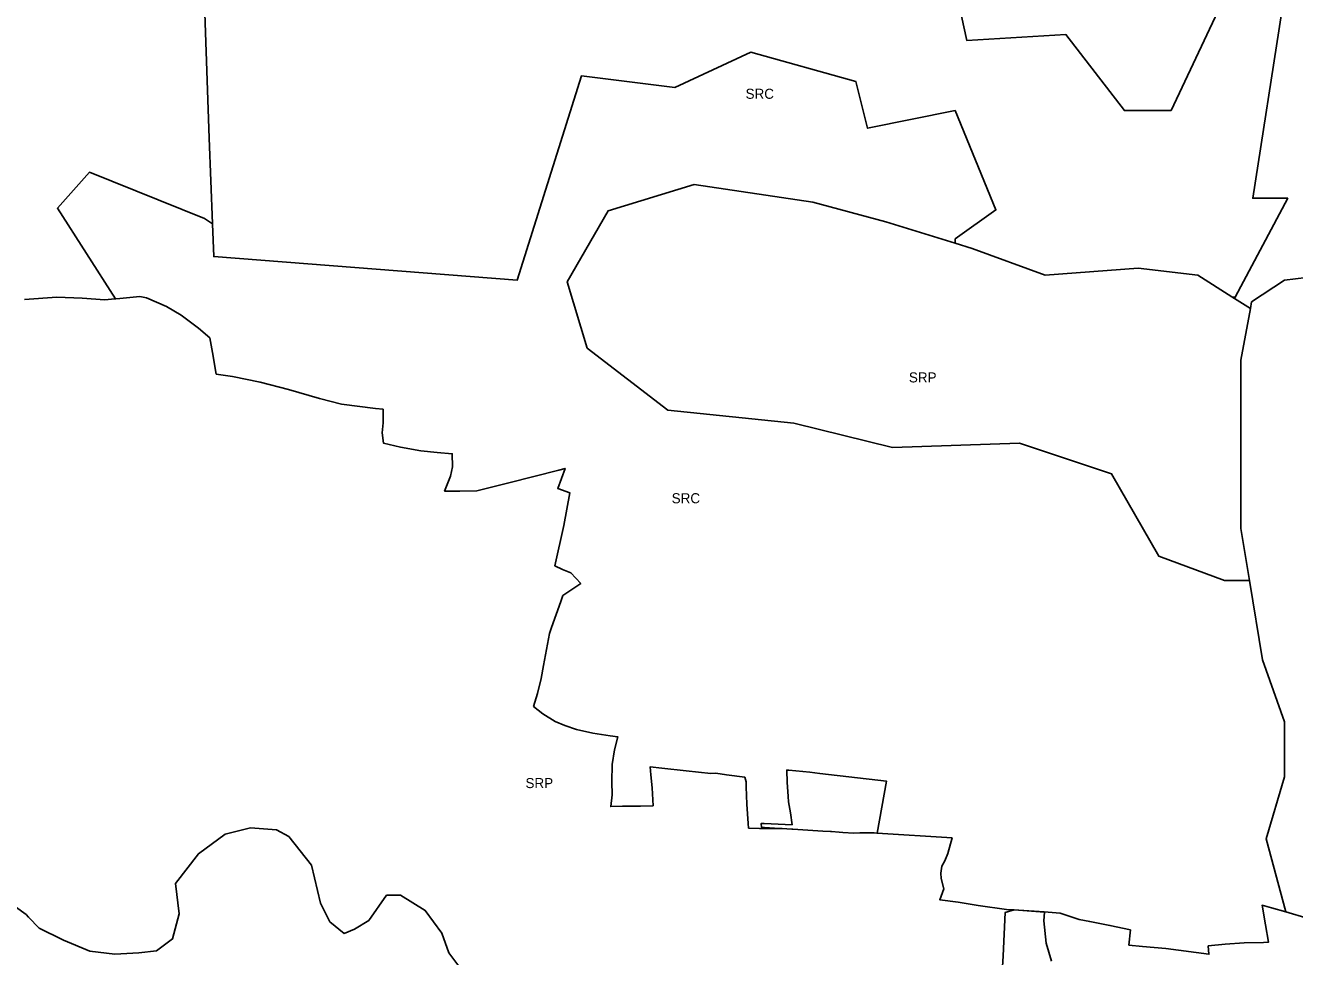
# Model space of a CAD drawing. Extents: x 598968 to 613553, y 4409678 to 4430833.
# Drawn here: x 601335 to 602848, y 4410591 to 4411701 of the extents above; entities that cross this region are included whole.
import ezdxf

# ---------------------------------------------------------------- set-up
doc = ezdxf.new("R2010")
doc.units = 0
for name, color, linetype in [('1', 7, 'Continuous'), ('Sòl Rústic Comú', 7, 'Continuous'), ('Sòl Rústic Protegit', 7, 'Continuous'), ('Sòl Rústic Protegit - Alt Nivell de Protecció', 7, 'Continuous')]:
    doc.layers.add(name, color=color, linetype=linetype)

msp = doc.modelspace()

# ---------------------------------------------------------------- linework, layer by layer
at = {"layer": '1'}
msp.add_lwpolyline([(602346.7629, 4410738.7608), (602350.3001, 4410738.7402), (602361.6351, 4410800.3432), (602282.0101, 4410809.5702), (602270.0801, 4410811.4102), (602244.9901, 4410813.7002), (602242.5701, 4410813.7002), (602243.2701, 4410799.0352), (602243.7841, 4410788.2652), (602244.3001, 4410782.1302), (602244.8161, 4410775.9952), (602247.0051, 4410762.7602), (602248.9791, 4410748.6272), (602215.8541, 4410750.1482), (602212.1451, 4410750.1482), (602212.3801, 4410745.1402), (602216.2601, 4410745.2502), (602228.1091, 4410744.5942), (602237.0101, 4410744.2102), (602248.5381, 4410743.465), (602249.0359, 4410743.4328), (602249.7101, 4410743.3892), (602285.8001, 4410741.0252), (602294.6517, 4410740.4454), (602294.6635, 4410740.4446), (602295.8981, 4410740.3638), (602305.2495, 4410739.7514), (602309.2523, 4410739.4892), (602322.5201, 4410738.6202), (602329.7301, 4410738.8602), (602345.9551, 4410738.7654)], close=True, dxfattribs=at)
at = {"layer": 'Sòl Rústic Comú'}
for points in [[(602422.3725, 4411843.1854), (602457.1223, 4411683.1854), (602575.3735, 4411690.1856), (602644.9363, 4411599.6856), (602700.5619, 4411599.6856), (602756.1879, 4411717.6858)], [(602756.1879, 4411717.6858), (602700.5619, 4411599.6856), (602644.9363, 4411599.6856), (602575.3735, 4411690.1856), (602457.1223, 4411683.1854), (602422.3725, 4411843.1854)], [(601547.3631, 4411773.1842), (601554.2999, 4411566.684), (601558.2995, 4411465.184), (601558.3193, 4411464.6848), (601559.8619, 4411425.684), (601921.5531, 4411397.6844), (601998.0547, 4411641.1848), (602109.3683, 4411627.1848), (602199.7445, 4411669.185), (602324.9957, 4411634.1852), (602338.8705, 4411578.6852), (602443.1843, 4411599.6852), (602491.9343, 4411481.1852), (602443.1837, 4411446.6852), (602443.1837, 4411441.6852), (602463.5589, 4411435.1852), (602550.5597, 4411403.6852), (602661.3109, 4411411.6854), (602732.4991, 4411403.6856), (602772.9369, 4411377.6856), (602777.0619, 4411377.1856), (602839.6879, 4411495.1858), (602797.9375, 4411495.1856), (602832.7513, 4411717.686)], [(602832.7513, 4411717.686), (602797.9375, 4411495.1856), (602839.6879, 4411495.1858), (602777.0619, 4411377.1856), (602772.9369, 4411377.6856), (602795.1245, 4411363.6856), (602796.6245, 4411371.6856), (602835.8125, 4411397.6856), (602875.0005, 4411402.1858)]]:
    msp.add_lwpolyline(points, dxfattribs=at)
msp.add_lwpolyline([(602443.1837, 4411441.6852), (602443.1837, 4411446.6852), (602491.9343, 4411481.1852), (602443.1843, 4411599.6852), (602338.8705, 4411578.6852), (602324.9957, 4411634.1852), (602199.7445, 4411669.185), (602109.3683, 4411627.1848), (601998.0547, 4411641.1848), (601921.5531, 4411397.6844), (601559.8619, 4411425.684), (601558.3193, 4411464.6848), (601548.9245, 4411471.184), (601411.6733, 4411526.1838), (601373.5477, 4411483.1838), (601442.8415, 4411375.2134), (601442.8605, 4411375.1838), (601447.8605, 4411375.6838), (601471.6107, 4411378.1838), (601479.4859, 4411376.6838), (601503.6735, 4411366.1838), (601520.9237, 4411355.6838), (601541.7363, 4411340.1838), (601554.9865, 4411328.6838), (601558.4865, 4411311.1838), (601562.7989, 4411285.6838), (601582.0491, 4411282.6838), (601615.1119, 4411276.1838), (601648.9247, 4411267.1838), (601685.9875, 4411256.684), (601712.1129, 4411249.684), (601752.6757, 4411244.684), (601761.5509, 4411243.684), (601761.8007, 4411227.684), (601760.3631, 4411215.684), (601762.2381, 4411203.184), (601782.3009, 4411198.684), (601806.6135, 4411194.184), (601825.9887, 4411192.184), (601843.9889, 4411190.684), (601844.4889, 4411175.184), (601841.8639, 4411164.184), (601834.8637, 4411146.184), (601852.8639, 4411146.184), (601873.2391, 4411146.684), (601911.3645, 4411156.1842), (601970.9277, 4411171.1842), (601978.4903, 4411173.1842), (601969.6777, 4411149.1842), (601984.0527, 4411144.1842), (601976.9901, 4411105.1842), (601966.1147, 4411057.1842), (601975.2399, 4411052.6842), (601985.3649, 4411048.6842), (601997.1149, 4411036.1842), (601985.3023, 4411028.1842), (601975.7397, 4411021.6842), (601973.5521, 4411014.6842), (601962.3019, 4410983.684), (601959.9893, 4410976.684), (601952.6767, 4410938.184), (601949.8015, 4410922.684), (601945.4265, 4410905.184), (601940.9889, 4410889.684), (601952.1139, 4410880.684), (601966.7391, 4410871.684), (601977.9891, 4410866.684), (601991.9267, 4410862.184), (602011.5519, 4410857.684), (602031.9897, 4410854.684), (602041.3647, 4410853.184), (602037.4271, 4410837.684), (602034.6145, 4410820.184), (602034.1769, 4410799.684), (602034.6769, 4410784.184), (602032.9269, 4410770.184), (602046.9895, 4410770.684), (602068.4273, 4410770.684), (602083.3023, 4410771.184), (602082.1149, 4410792.684), (602080.6775, 4410808.184), (602079.8651, 4410817.684), (602093.8027, 4410816.184), (602122.6155, 4410812.6842), (602152.0533, 4410809.6842), (602158.0533, 4410810.1842), (602170.9285, 4410808.1842), (602192.4911, 4410805.1842), (602194.1161, 4410799.6842), (602194.3661, 4410793.6842), (602195.2411, 4410773.1842), (602196.7409, 4410750.1842), (602197.1159, 4410744.6842), (602210.1161, 4410744.1842), (602210.2967, 4410744.1814), (602242.6165, 4410743.6842), (602248.5381, 4410743.465), (602237.0101, 4410744.2102), (602228.1091, 4410744.5942), (602216.2601, 4410745.2502), (602212.3801, 4410745.1402), (602212.1451, 4410750.1482), (602215.8541, 4410750.1482), (602248.9791, 4410748.6272), (602247.0051, 4410762.7602), (602244.8161, 4410775.9952), (602244.3001, 4410782.1302), (602243.7841, 4410788.2652), (602243.2701, 4410799.0352), (602242.5701, 4410813.7002), (602244.9901, 4410813.7002), (602270.0801, 4410811.4102), (602282.0101, 4410809.5702), (602361.6351, 4410800.3432), (602350.3001, 4410738.7402), (602346.7629, 4410738.7608), (602349.8675, 4410738.6844), (602350.3111, 4410738.6572), (602439.5559, 4410733.1844), (602434.4309, 4410714.1844), (602430.8057, 4410705.6844), (602427.3057, 4410699.1844), (602426.3681, 4410690.6844), (602426.5557, 4410684.6844), (602429.8681, 4410672.1844), (602424.9929, 4410659.1844), (602446.8057, 4410656.1844), (602470.8685, 4410652.1844), (602504.4313, 4410647.6844), (602513.1189, 4410647.1846), (602549.3067, 4410644.6846), (602568.3695, 4410643.1846), (602580.1821, 4410639.1846), (602591.2447, 4410635.6846), (602603.6197, 4410633.1846), (602627.8075, 4410628.6846), (602652.0577, 4410623.1846), (602650.3701, 4410605.1846), (602666.3703, 4410603.6846), (602694.4955, 4410601.1848), (602745.6835, 4410594.1848), (602744.8711, 4410604.1848), (602764.8713, 4410606.1848), (602787.6841, 4410607.6848), (602810.8093, 4410608.1848), (602816.8719, 4410608.6848), (602813.0595, 4410629.185), (602808.9969, 4410652.685), (602820.4345, 4410649.685), (602837.4187, 4410644.631), (602837.4069, 4410644.675), (602814.0599, 4410731.685), (602835.8103, 4410805.6852), (602835.8105, 4410871.1852), (602809.6855, 4410945.1852), (602793.9357, 4411039.6852), (602764.1229, 4411039.6852), (602685.8097, 4411068.6852), (602629.6221, 4411166.6852), (602519.8085, 4411203.185), (602368.6195, 4411198.1848), (602250.9933, 4411227.1846), (602100.7419, 4411242.6844), (602004.8037, 4411316.6844), (601981.1161, 4411395.6844), (602029.6169, 4411480.1846), (602132.3681, 4411511.6848), (602273.7445, 4411490.685), (602360.7453, 4411467.185)], close=True, dxfattribs=at)
at = {"layer": 'Sòl Rústic Protegit'}
for points in [[(601334.2969, 4411374.6836), (601372.6723, 4411377.1836), (601403.1725, 4411376.1836), (601429.8603, 4411374.1836), (601437.9981, 4411374.8096), (601442.8605, 4411375.1838), (601442.8415, 4411375.2134), (601373.5477, 4411483.1838), (601411.6733, 4411526.1838), (601548.9245, 4411471.184), (601558.3193, 4411464.6848), (601558.2995, 4411465.184), (601554.2999, 4411566.684), (601547.3631, 4411773.1842)], [(602875.0005, 4411402.1858), (602835.8125, 4411397.6856), (602796.6245, 4411371.6856), (602795.1245, 4411363.6856), (602783.5617, 4411302.1854), (602783.5609, 4411101.6854), (602793.9357, 4411039.6852), (602809.6855, 4410945.1852), (602835.8105, 4410871.1852), (602835.8103, 4410805.6852), (602814.0599, 4410731.685), (602837.4069, 4410644.675), (602837.4187, 4410644.631), (602864.1225, 4410636.685)], [(602864.1225, 4410636.685), (602837.4187, 4410644.631), (602820.4345, 4410649.685), (602808.9969, 4410652.685), (602813.0595, 4410629.185), (602816.8719, 4410608.6848), (602810.8093, 4410608.1848), (602787.6841, 4410607.6848), (602764.8713, 4410606.1848), (602744.8711, 4410604.1848), (602745.6835, 4410594.1848), (602694.4955, 4410601.1848), (602666.3703, 4410603.6846), (602650.3701, 4410605.1846), (602652.0577, 4410623.1846), (602627.8075, 4410628.6846), (602603.6197, 4410633.1846), (602591.2447, 4410635.6846), (602580.1821, 4410639.1846), (602568.3695, 4410643.1846), (602549.3067, 4410644.6846), (602513.1189, 4410647.1846), (602504.4313, 4410647.6844), (602470.8685, 4410652.1844), (602446.8057, 4410656.1844), (602424.9929, 4410659.1844), (602429.8681, 4410672.1844), (602426.5557, 4410684.6844), (602426.3681, 4410690.6844), (602427.3057, 4410699.1844), (602430.8057, 4410705.6844), (602434.4309, 4410714.1844), (602439.5559, 4410733.1844), (602350.3111, 4410738.6572), (602349.8675, 4410738.6844), (602346.7629, 4410738.7608), (602345.9551, 4410738.7654), (602329.7301, 4410738.8602), (602322.5201, 4410738.6202), (602309.2523, 4410739.4892), (602305.2495, 4410739.7514), (602295.8981, 4410740.3638), (602294.6635, 4410740.4446), (602294.6517, 4410740.4454), (602285.8001, 4410741.0252), (602249.7101, 4410743.3892), (602249.0359, 4410743.4328), (602248.5381, 4410743.465), (602242.6165, 4410743.6842), (602210.2967, 4410744.1814), (602210.1161, 4410744.1842), (602197.1159, 4410744.6842), (602196.7409, 4410750.1842), (602195.2411, 4410773.1842), (602194.3661, 4410793.6842), (602194.1161, 4410799.6842), (602192.4911, 4410805.1842), (602170.9285, 4410808.1842), (602158.0533, 4410810.1842), (602152.0533, 4410809.6842), (602122.6155, 4410812.6842), (602093.8027, 4410816.184), (602079.8651, 4410817.684), (602080.6775, 4410808.184), (602082.1149, 4410792.684), (602083.3023, 4410771.184), (602068.4273, 4410770.684), (602046.9895, 4410770.684), (602032.9269, 4410770.184), (602034.6769, 4410784.184), (602034.1769, 4410799.684), (602034.6145, 4410820.184), (602037.4271, 4410837.684), (602041.3647, 4410853.184), (602031.9897, 4410854.684), (602011.5519, 4410857.684), (601991.9267, 4410862.184), (601977.9891, 4410866.684), (601966.7391, 4410871.684), (601952.1139, 4410880.684), (601940.9889, 4410889.684), (601945.4265, 4410905.184), (601949.8015, 4410922.684), (601952.6767, 4410938.184), (601959.9893, 4410976.684), (601962.3019, 4410983.684), (601973.5521, 4411014.6842), (601975.7397, 4411021.6842), (601985.3023, 4411028.1842), (601997.1149, 4411036.1842), (601985.3649, 4411048.6842), (601975.2399, 4411052.6842), (601966.1147, 4411057.1842), (601976.9901, 4411105.1842), (601984.0527, 4411144.1842), (601969.6777, 4411149.1842), (601978.4903, 4411173.1842), (601970.9277, 4411171.1842), (601911.3645, 4411156.1842), (601873.2391, 4411146.684), (601852.8639, 4411146.184), (601834.8637, 4411146.184), (601841.8639, 4411164.184), (601844.4889, 4411175.184), (601843.9889, 4411190.684), (601825.9887, 4411192.184), (601806.6135, 4411194.184), (601782.3009, 4411198.684), (601762.2381, 4411203.184), (601760.3631, 4411215.684), (601761.8007, 4411227.684), (601761.5509, 4411243.684), (601752.6757, 4411244.684), (601712.1129, 4411249.684), (601685.9875, 4411256.684), (601648.9247, 4411267.1838), (601615.1119, 4411276.1838), (601582.0491, 4411282.6838), (601562.7989, 4411285.6838), (601558.4865, 4411311.1838), (601554.9865, 4411328.6838), (601541.7363, 4411340.1838), (601520.9237, 4411355.6838), (601503.6735, 4411366.1838), (601479.4859, 4411376.6838), (601471.6107, 4411378.1838), (601447.8605, 4411375.6838), (601442.8605, 4411375.1838), (601437.9981, 4411374.8096), (601429.8603, 4411374.1836), (601403.1725, 4411376.1836), (601372.6723, 4411377.1836), (601334.2969, 4411374.6836)], [(601310.8051, 4410660.0098), (601336.4301, 4410641.5098), (601339.2427, 4410638.5098), (601351.7427, 4410625.5098), (601379.8051, 4410611.5098), (601380.8051, 4410611.0098), (601412.2427, 4410598.0098), (601441.8051, 4410594.5098), (601470.4927, 4410596.0098), (601491.4927, 4410598.5098), (601510.8051, 4410612.5098), (601518.6177, 4410642.5098), (601514.0551, 4410678.5098), (601541.4927, 4410714.0098), (601573.2427, 4410737.5098), (601603.6177, 4410745.0098), (601634.4301, 4410742.5098), (601649.4301, 4410734.5098), (601676.2427, 4410700.5098), (601686.9301, 4410655.0098), (601697.9927, 4410633.0098), (601715.1177, 4410619.0098), (601727.6801, 4410624.0098), (601744.5551, 4410634.5098), (601765.8051, 4410664.5098), (601782.4301, 4410664.5098), (601811.8677, 4410646.5098), (601831.4301, 4410619.5098), (601839.9927, 4410596.0098), (601854.1177, 4410577.0098)], [(602498.1177, 4410553.0098), (602500.4927, 4410592.5098), (602503.0551, 4410644.0098), (602513.5551, 4410647.0098), (602549.7427, 4410644.5098), (602548.8051, 4410634.0098), (602551.6801, 4410607.5098), (602558.2427, 4410586.0098)]]:
    msp.add_lwpolyline(points, dxfattribs=at)
msp.add_lwpolyline([(602443.1837, 4411441.6852), (602360.7453, 4411467.185), (602273.7445, 4411490.685), (602132.3681, 4411511.6848), (602029.6169, 4411480.1846), (601981.1161, 4411395.6844), (602004.8037, 4411316.6844), (602100.7419, 4411242.6844), (602250.9933, 4411227.1846), (602368.6195, 4411198.1848), (602519.8085, 4411203.185), (602629.6221, 4411166.6852), (602685.8097, 4411068.6852), (602764.1229, 4411039.6852), (602793.9357, 4411039.6852), (602783.5609, 4411101.6854), (602783.5617, 4411302.1854), (602795.1245, 4411363.6856), (602772.9369, 4411377.6856), (602732.4991, 4411403.6856), (602661.3109, 4411411.6854), (602550.5597, 4411403.6852), (602463.5589, 4411435.1852)], close=True, dxfattribs=at)
at = {"layer": 'Sòl Rústic Protegit - Alt Nivell de Protecció'}
for points in [[(601854.1177, 4410577.0098), (601839.9927, 4410596.0098), (601831.4301, 4410619.5098), (601811.8677, 4410646.5098), (601782.4301, 4410664.5098), (601765.8051, 4410664.5098), (601744.5551, 4410634.5098), (601727.6801, 4410624.0098), (601715.1177, 4410619.0098), (601697.9927, 4410633.0098), (601686.9301, 4410655.0098), (601676.2427, 4410700.5098), (601649.4301, 4410734.5098), (601634.4301, 4410742.5098), (601603.6177, 4410745.0098), (601573.2427, 4410737.5098), (601541.4927, 4410714.0098), (601514.0551, 4410678.5098), (601518.6177, 4410642.5098), (601510.8051, 4410612.5098), (601491.4927, 4410598.5098), (601470.4927, 4410596.0098), (601441.8051, 4410594.5098), (601412.2427, 4410598.0098), (601380.8051, 4410611.0098), (601379.8051, 4410611.5098), (601351.7427, 4410625.5098), (601339.2427, 4410638.5098), (601336.4301, 4410641.5098), (601310.8051, 4410660.0098)], [(602558.2427, 4410586.0098), (602551.6801, 4410607.5098), (602548.8051, 4410634.0098), (602549.7427, 4410644.5098), (602513.5551, 4410647.0098), (602503.0551, 4410644.0098), (602500.4927, 4410592.5098), (602498.1177, 4410553.0098)]]:
    msp.add_lwpolyline(points, dxfattribs=at)

# ---------------------------------------------------------------- texts
at = {"layer": 'Sòl Rústic Comú'}
for p in [(602193.5255, 4411613.6855), (602105.4832, 4411131.6849)]:
    msp.add_text('SRC', height=12, dxfattribs=at).set_placement(p)
at = {"layer": 'Sòl Rústic Protegit'}
for p in [(602388.1203, 4411275.685), (601931.27, 4410792.2427)]:
    msp.add_text('SRP', height=12, dxfattribs=at).set_placement(p)

doc.saveas('drawing.dxf')
